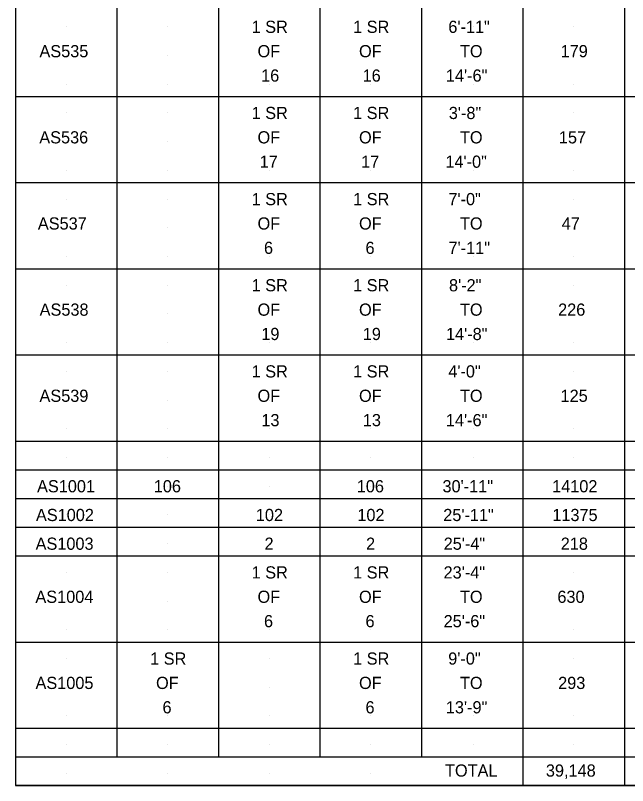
# Model space of a CAD drawing. Extents: x 2.9 to 17.4, y 3.2 to 21.1.
# Drawn here: x 2.87 to 9.91, y 3.22 to 12.07 of the extents above; entities that cross this region are included whole.
import ezdxf

# ---------------------------------------------------------------- set-up
doc = ezdxf.new("R2010")
doc.units = 0
for name, color, linetype in [('BR_P_Gen_Text', 7, 'Continuous'), ('Default', 7, 'Continuous'), ('SC_Scratch1', 7, 'Continuous')]:
    doc.layers.add(name, color=color, linetype=linetype)

msp = doc.modelspace()

# ---------------------------------------------------------------- linework, layer by layer
at = {"layer": 'BR_P_Gen_Text'}
for p, q in [((4.0352, 20.0019), (4.0352, 3.5519)), ((5.2019, 20.0019), (5.2019, 3.5519)), ((6.3686, 20.0019), (6.3686, 3.5519)), ((7.5353, 20.0019), (7.5353, 3.5519)), ((8.702, 20.0019), (8.702, 3.2219)), ((9.8686, 20.0019), (9.8686, 3.2219)), ((2.8685, 11.1419), (17.3686, 11.1419)), ((2.8685, 10.1519), (17.3686, 10.1519)), ((2.8685, 9.1619), (17.3686, 9.1619)), ((2.8685, 8.1719), (17.3686, 8.1719)), ((2.8685, 7.1819), (17.3686, 7.1819)), ((2.8685, 6.8519), (17.3686, 6.8519)), ((2.8685, 6.5219), (17.3686, 6.5219)), ((2.8685, 6.1919), (17.3686, 6.1919)), ((2.8685, 5.8619), (17.3686, 5.8619)), ((2.8685, 5.8619), (17.3686, 5.8619)), ((2.8685, 4.8719), (17.3686, 4.8719)), ((2.8685, 3.8819), (17.3686, 3.8819)), ((2.8685, 3.5519), (17.3686, 3.5519)), ((2.8685, 3.5519), (17.3686, 3.5519)), ((17.3686, 3.2219), (2.8685, 3.2219)), ((2.8685, 3.2219), (17.3686, 3.2219)), ((2.8685, 3.2219), (17.3686, 3.2219))]:
    msp.add_line(p, q, dxfattribs=at)
at = {"layer": 'Default'}
msp.add_line((2.8685, 21.0518), (2.8685, 3.2219), dxfattribs=at)
at = {"layer": 'SC_Scratch1'}
for p, q in [((3.4518, 11.9419), (3.4518, 11.9419)), ((3.4518, 11.9419), (3.4518, 11.9419)), ((4.6185, 11.9419), (4.6185, 11.9419)), ((5.7852, 11.9419), (5.7852, 11.9419)), ((6.9519, 11.9419), (6.9519, 11.9419)), ((8.1395, 11.9419), (8.1395, 11.9419)), ((8.1395, 11.9419), (8.1395, 11.9419)), ((9.2853, 11.9419), (9.2853, 11.9419)), ((9.2853, 11.9419), (9.2853, 11.9419)), ((3.4518, 11.6119), (3.4518, 11.6119)), ((4.6185, 11.6119), (4.6185, 11.6119)), ((5.7852, 11.6119), (5.7852, 11.6119)), ((6.9519, 11.6119), (6.9519, 11.6119)), ((8.1395, 11.6119), (8.1395, 11.6119)), ((8.1395, 11.6119), (8.1395, 11.6119)), ((9.2853, 11.6119), (9.2853, 11.6119)), ((9.2853, 11.6119), (9.2853, 11.6119)), ((3.4518, 11.2819), (3.4518, 11.2819)), ((4.6185, 11.2819), (4.6185, 11.2819)), ((5.7852, 11.2819), (5.7852, 11.2819)), ((6.9519, 11.2819), (6.9519, 11.2819)), ((8.1395, 11.2819), (8.1395, 11.2819)), ((8.1395, 11.2819), (8.1395, 11.2819)), ((9.2853, 11.2819), (9.2853, 11.2819)), ((9.2853, 11.2819), (9.2853, 11.2819)), ((3.4518, 10.9519), (3.4518, 10.9519)), ((4.6185, 10.9519), (4.6185, 10.9519)), ((5.7852, 10.9519), (5.7852, 10.9519)), ((6.9519, 10.9519), (6.9519, 10.9519)), ((8.1395, 10.9519), (8.1395, 10.9519)), ((8.1395, 10.9519), (8.1395, 10.9519)), ((9.2853, 10.9519), (9.2853, 10.9519)), ((9.2853, 10.9519), (9.2853, 10.9519)), ((3.4518, 10.6219), (3.4518, 10.6219)), ((4.6185, 10.6219), (4.6185, 10.6219)), ((5.7852, 10.6219), (5.7852, 10.6219)), ((6.9519, 10.6219), (6.9519, 10.6219)), ((8.1395, 10.6219), (8.1395, 10.6219)), ((8.1395, 10.6219), (8.1395, 10.6219)), ((9.2853, 10.6219), (9.2853, 10.6219)), ((9.2853, 10.6219), (9.2853, 10.6219)), ((3.4518, 10.2919), (3.4518, 10.2919)), ((4.6185, 10.2919), (4.6185, 10.2919)), ((5.7852, 10.2919), (5.7852, 10.2919)), ((6.9519, 10.2919), (6.9519, 10.2919)), ((8.1395, 10.2919), (8.1395, 10.2919)), ((8.1395, 10.2919), (8.1395, 10.2919)), ((9.2853, 10.2919), (9.2853, 10.2919)), ((9.2853, 10.2919), (9.2853, 10.2919)), ((3.4518, 9.9619), (3.4518, 9.9619)), ((4.6185, 9.9619), (4.6185, 9.9619)), ((5.7852, 9.9619), (5.7852, 9.9619)), ((6.9519, 9.9619), (6.9519, 9.9619)), ((8.1395, 9.9619), (8.1395, 9.9619)), ((8.1395, 9.9619), (8.1395, 9.9619)), ((9.2853, 9.9619), (9.2853, 9.9619)), ((9.2853, 9.9619), (9.2853, 9.9619)), ((3.4518, 9.6319), (3.4518, 9.6319)), ((4.6185, 9.6319), (4.6185, 9.6319)), ((5.7852, 9.6319), (5.7852, 9.6319)), ((6.9519, 9.6319), (6.9519, 9.6319)), ((8.1395, 9.6319), (8.1395, 9.6319)), ((8.1395, 9.6319), (8.1395, 9.6319)), ((9.2853, 9.6319), (9.2853, 9.6319)), ((9.2853, 9.6319), (9.2853, 9.6319)), ((3.4518, 9.3019), (3.4518, 9.3019)), ((4.6185, 9.3019), (4.6185, 9.3019)), ((5.7852, 9.3019), (5.7852, 9.3019)), ((6.9519, 9.3019), (6.9519, 9.3019)), ((8.1395, 9.3019), (8.1395, 9.3019)), ((8.1395, 9.3019), (8.1395, 9.3019)), ((9.2853, 9.3019), (9.2853, 9.3019)), ((9.2853, 9.3019), (9.2853, 9.3019)), ((3.4518, 8.9719), (3.4518, 8.9719)), ((4.6185, 8.9719), (4.6185, 8.9719)), ((5.7852, 8.9719), (5.7852, 8.9719)), ((6.9519, 8.9719), (6.9519, 8.9719)), ((8.1395, 8.9719), (8.1395, 8.9719)), ((8.1395, 8.9719), (8.1395, 8.9719)), ((9.2853, 8.9719), (9.2853, 8.9719)), ((9.2853, 8.9719), (9.2853, 8.9719)), ((3.4518, 8.6419), (3.4518, 8.6419)), ((4.6185, 8.6419), (4.6185, 8.6419)), ((5.7852, 8.6419), (5.7852, 8.6419)), ((6.9519, 8.6419), (6.9519, 8.6419)), ((8.1395, 8.6419), (8.1395, 8.6419)), ((8.1395, 8.6419), (8.1395, 8.6419)), ((9.2853, 8.6419), (9.2853, 8.6419)), ((9.2853, 8.6419), (9.2853, 8.6419)), ((3.4518, 8.3119), (3.4518, 8.3119)), ((4.6185, 8.3119), (4.6185, 8.3119)), ((5.7852, 8.3119), (5.7852, 8.3119)), ((6.9519, 8.3119), (6.9519, 8.3119)), ((8.1395, 8.3119), (8.1395, 8.3119)), ((8.1395, 8.3119), (8.1395, 8.3119)), ((9.2853, 8.3119), (9.2853, 8.3119)), ((9.2853, 8.3119), (9.2853, 8.3119)), ((3.4518, 7.9819), (3.4518, 7.9819)), ((4.6185, 7.9819), (4.6185, 7.9819)), ((5.7852, 7.9819), (5.7852, 7.9819)), ((6.9519, 7.9819), (6.9519, 7.9819)), ((8.1395, 7.9819), (8.1395, 7.9819)), ((8.1395, 7.9819), (8.1395, 7.9819)), ((9.2853, 7.9819), (9.2853, 7.9819)), ((9.2853, 7.9819), (9.2853, 7.9819)), ((3.4518, 7.6519), (3.4518, 7.6519)), ((4.6185, 7.6519), (4.6185, 7.6519)), ((5.7852, 7.6519), (5.7852, 7.6519)), ((6.9519, 7.6519), (6.9519, 7.6519)), ((8.1395, 7.6519), (8.1395, 7.6519)), ((8.1395, 7.6519), (8.1395, 7.6519)), ((9.2853, 7.6519), (9.2853, 7.6519)), ((9.2853, 7.6519), (9.2853, 7.6519)), ((3.4518, 7.3219), (3.4518, 7.3219)), ((4.6185, 7.3219), (4.6185, 7.3219)), ((5.7852, 7.3219), (5.7852, 7.3219)), ((6.9519, 7.3219), (6.9519, 7.3219)), ((8.1395, 7.3219), (8.1395, 7.3219)), ((8.1395, 7.3219), (8.1395, 7.3219)), ((9.2853, 7.3219), (9.2853, 7.3219)), ((9.2853, 7.3219), (9.2853, 7.3219)), ((3.4518, 6.9919), (3.4518, 6.9919)), ((4.6185, 6.9919), (4.6185, 6.9919)), ((5.7852, 6.9919), (5.7852, 6.9919)), ((6.9519, 6.9919), (6.9519, 6.9919)), ((8.1395, 6.9919), (8.1395, 6.9919)), ((8.1395, 6.9919), (8.1395, 6.9919)), ((9.2853, 6.9919), (9.2853, 6.9919)), ((9.2853, 6.9919), (9.2853, 6.9919)), ((3.4518, 6.6619), (3.4518, 6.6619)), ((4.6185, 6.6619), (4.6185, 6.6619)), ((5.7852, 6.6619), (5.7852, 6.6619)), ((6.9519, 6.6619), (6.9519, 6.6619)), ((8.1395, 6.6619), (8.1395, 6.6619)), ((8.1395, 6.6619), (8.1395, 6.6619)), ((9.2853, 6.6619), (9.2853, 6.6619)), ((9.2853, 6.6619), (9.2853, 6.6619)), ((3.4518, 6.3319), (3.4518, 6.3319)), ((4.6185, 6.3319), (4.6185, 6.3319)), ((5.7852, 6.3319), (5.7852, 6.3319)), ((6.9519, 6.3319), (6.9519, 6.3319)), ((8.1395, 6.3319), (8.1395, 6.3319)), ((8.1395, 6.3319), (8.1395, 6.3319)), ((9.2853, 6.3319), (9.2853, 6.3319)), ((9.2853, 6.3319), (9.2853, 6.3319)), ((3.4518, 6.0019), (3.4518, 6.0019)), ((4.6185, 6.0019), (4.6185, 6.0019)), ((5.7852, 6.0019), (5.7852, 6.0019)), ((6.9519, 6.0019), (6.9519, 6.0019)), ((8.1395, 6.0019), (8.1395, 6.0019)), ((8.1395, 6.0019), (8.1395, 6.0019)), ((9.2853, 6.0019), (9.2853, 6.0019)), ((9.2853, 6.0019), (9.2853, 6.0019)), ((3.4518, 5.6719), (3.4518, 5.6719)), ((4.6185, 5.6719), (4.6185, 5.6719)), ((5.7852, 5.6719), (5.7852, 5.6719)), ((6.9519, 5.6719), (6.9519, 5.6719)), ((8.1395, 5.6719), (8.1395, 5.6719)), ((8.1395, 5.6719), (8.1395, 5.6719)), ((9.2853, 5.6719), (9.2853, 5.6719)), ((9.2853, 5.6719), (9.2853, 5.6719)), ((3.4518, 5.3419), (3.4518, 5.3419)), ((4.6185, 5.3419), (4.6185, 5.3419)), ((5.7852, 5.3419), (5.7852, 5.3419)), ((6.9519, 5.3419), (6.9519, 5.3419)), ((8.1395, 5.3419), (8.1395, 5.3419)), ((8.1395, 5.3419), (8.1395, 5.3419)), ((9.2853, 5.3419), (9.2853, 5.3419)), ((9.2853, 5.3419), (9.2853, 5.3419)), ((3.4518, 5.0119), (3.4518, 5.0119)), ((4.6185, 5.0119), (4.6185, 5.0119)), ((5.7852, 5.0119), (5.7852, 5.0119)), ((6.9519, 5.0119), (6.9519, 5.0119)), ((8.1395, 5.0119), (8.1395, 5.0119)), ((8.1395, 5.0119), (8.1395, 5.0119)), ((9.2853, 5.0119), (9.2853, 5.0119)), ((9.2853, 5.0119), (9.2853, 5.0119)), ((3.4518, 4.6819), (3.4518, 4.6819)), ((4.6185, 4.6819), (4.6185, 4.6819)), ((5.7852, 4.6819), (5.7852, 4.6819)), ((6.9519, 4.6819), (6.9519, 4.6819)), ((8.1395, 4.6819), (8.1395, 4.6819)), ((8.1395, 4.6819), (8.1395, 4.6819)), ((9.2853, 4.6819), (9.2853, 4.6819)), ((9.2853, 4.6819), (9.2853, 4.6819)), ((3.4518, 4.3519), (3.4518, 4.3519)), ((4.6185, 4.3519), (4.6185, 4.3519)), ((5.7852, 4.3519), (5.7852, 4.3519)), ((6.9519, 4.3519), (6.9519, 4.3519)), ((8.1395, 4.3519), (8.1395, 4.3519)), ((8.1395, 4.3519), (8.1395, 4.3519)), ((9.2853, 4.3519), (9.2853, 4.3519)), ((9.2853, 4.3519), (9.2853, 4.3519)), ((3.4518, 4.0219), (3.4518, 4.0219)), ((4.6185, 4.0219), (4.6185, 4.0219)), ((5.7852, 4.0219), (5.7852, 4.0219)), ((6.9519, 4.0219), (6.9519, 4.0219)), ((8.1395, 4.0219), (8.1395, 4.0219)), ((8.1395, 4.0219), (8.1395, 4.0219)), ((9.2853, 4.0219), (9.2853, 4.0219)), ((9.2853, 4.0219), (9.2853, 4.0219)), ((3.4518, 3.6919), (3.4518, 3.6919)), ((4.6185, 3.6919), (4.6185, 3.6919)), ((5.7852, 3.6919), (5.7852, 3.6919)), ((6.9519, 3.6919), (6.9519, 3.6919)), ((8.1395, 3.6919), (8.1395, 3.6919)), ((8.1395, 3.6919), (8.1395, 3.6919)), ((9.2853, 3.6919), (9.2853, 3.6919)), ((9.2853, 3.6919), (9.2853, 3.6919)), ((3.4518, 3.3619), (3.4518, 3.3619)), ((4.6185, 3.3619), (4.6185, 3.3619)), ((5.7852, 3.3619), (5.7852, 3.3619)), ((6.9519, 3.3619), (6.9519, 3.3619)), ((8.1395, 3.3619), (8.1395, 3.3619)), ((8.1395, 3.3619), (8.1395, 3.3619)), ((9.2853, 3.3619), (9.2853, 3.3619)), ((9.2853, 3.3619), (9.2853, 3.3619))]:
    msp.add_line(p, q, dxfattribs=at)

# ---------------------------------------------------------------- texts
at = {"layer": 'BR_P_Gen_Text'}
for s, p in [('1 SR', (5.5841, 11.8719)), ('1 SR', (6.7508, 11.8719)), ('6\'-11"', (7.8454, 11.8719)), ('AS535', (3.1449, 11.5919)), ('OF', (5.6519, 11.5919)), ('OF', (6.8186, 11.5919)), ('TO', (7.9792, 11.5919)), ('179', (9.136, 11.5919)), ('16', (5.6932, 11.3119)), ('16', (6.8599, 11.3119)), ('14\'-6"', (7.8172, 11.3119)), ('1 SR', (5.5841, 10.8819)), ('1 SR', (6.7508, 10.8819)), ('3\'-8"', (7.8508, 10.8819)), ('AS536', (3.1432, 10.6019)), ('OF', (5.6519, 10.6019)), ('OF', (6.8186, 10.6019)), ('TO', (7.9792, 10.6019)), ('157', (9.1162, 10.6019)), ('17', (5.6767, 10.3219)), ('17', (6.8434, 10.3219)), ('14\'-0"', (7.8117, 10.3219)), ('1 SR', (5.5841, 9.8919)), ('1 SR', (6.7508, 9.8919)), ('7\'-0"', (7.8464, 9.8919)), ('AS537', (3.1267, 9.6119)), ('OF', (5.6519, 9.6119)), ('OF', (6.8186, 9.6119)), ('TO', (7.9792, 9.6119)), ('47', (9.1487, 9.6119)), ('6', (5.7263, 9.3319)), ('6', (6.893, 9.3319)), ('7\'-11"', (7.8476, 9.3319)), ('1 SR', (5.5841, 8.9019)), ('1 SR', (6.7508, 8.9019)), ('8\'-2"', (7.853, 8.9019)), ('AS538', (3.1471, 8.6219)), ('OF', (5.6519, 8.6219)), ('OF', (6.8186, 8.6219)), ('TO', (7.9792, 8.6219)), ('226', (9.1073, 8.6219)), ('19', (5.6954, 8.3419)), ('19', (6.8621, 8.3419)), ('14\'-8"', (7.8183, 8.3419)), ('1 SR', (5.5841, 7.9119)), ('1 SR', (6.7508, 7.9119)), ('4\'-0"', (7.8447, 7.9119)), ('AS539', (3.1454, 7.6319)), ('OF', (5.6519, 7.6319)), ('OF', (6.8186, 7.6319)), ('TO', (7.9792, 7.6319)), ('125', (9.1355, 7.6319)), ('13', (5.696, 7.3519)), ('13', (6.8627, 7.3519)), ('14\'-6"', (7.8172, 7.3519)), ('AS1001', (3.1173, 6.5919)), ('106', (4.4593, 6.5919)), ('106', (6.7927, 6.5919)), ('30\'-11"', (7.7781, 6.5919)), ('14102', (9.0385, 6.5919)), ('AS1002', (3.1047, 6.2619)), ('102', (5.6326, 6.2619)), ('102', (6.7993, 6.2619)), ('25\'-11"', (7.7869, 6.2619)), ('11375', (9.0407, 6.2619)), ('AS1003', (3.1008, 5.9319)), ('2', (5.7329, 5.9319)), ('2', (6.8996, 5.9319)), ('25\'-4"', (7.7918, 5.9319)), ('218', (9.1377, 5.9319)), ('1 SR', (5.5841, 5.6019)), ('1 SR', (6.7508, 5.6019)), ('23\'-4"', (7.7907, 5.6019)), ('AS1004', (3.0986, 5.3219)), ('OF', (5.6519, 5.3219)), ('OF', (6.8186, 5.3219)), ('TO', (7.9792, 5.3219)), ('630', (9.0991, 5.3219)), ('6', (5.7263, 5.0419)), ('6', (6.893, 5.0419)), ('25\'-6"', (7.7913, 5.0419)), ('1 SR', (4.4174, 4.6119)), ('1 SR', (6.7508, 4.6119)), ('9\'-0"', (7.8442, 4.6119)), ('AS1005', (3.0997, 4.3319)), ('OF', (4.4852, 4.3319)), ('OF', (6.8186, 4.3319)), ('TO', (7.9792, 4.3319)), ('293', (9.1079, 4.3319)), ('6', (4.5596, 4.0519)), ('6', (6.893, 4.0519)), ('13\'-9"', (7.8167, 4.0519)), ('TOTAL', (7.8073, 3.3251)), ('39,148', (8.9668, 3.3251))]:
    msp.add_text(s, height=0.14, dxfattribs=at).set_placement(p)

doc.saveas('drawing.dxf')
